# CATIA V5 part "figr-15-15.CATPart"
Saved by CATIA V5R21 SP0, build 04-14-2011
Part number: Part1
Bounding box of the stored display mesh (mm): x -75 to 75, y -66.397 to 33.603, z 0 to 1
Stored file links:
  D:\CATIA V5R21 E-RESOURCES\CATIA-V5R21\catia-v5r21-prt\c15-catia-v5r20-prt\c15-catia-v5r21-figr-15-15.CATPart
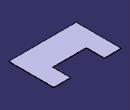
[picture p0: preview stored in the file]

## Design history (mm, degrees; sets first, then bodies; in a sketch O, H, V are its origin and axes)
SheetMetalParameters1: Thickness 1, BendRadius 1, KFactor 0.325257 {= log(min(100,max(20*SheetMetalParameters1.BendRadius,SheetMetalParameters1.Thickness)/SheetMetalParameters1.Thickness))/log(100)/2}, ReliefRadialLength 1, ReliefAxialLength 2, MinimumBendRadius 0
Body1 (main body)
  Sketch1 on xy-plane, origin (0, 0, 0), H (1, 0, 0), V (0, 1, 0)
    line L1 (-37.5, 33.6029) -> (-37.5, -6.3971)
    line L2 (-37.5, -6.3971) -> (37.5, -6.3971)
    line L3 (37.5, -6.3971) -> (37.5, 33.6029)
    line L4 (37.5, 33.6029) -> (75, 33.6029)
    line L5 (75, 33.6029) -> (75, -66.3971)
    line L6 (75, -66.3971) -> (-75, -66.3971)
    line L7 (-75, -66.3971) -> (-75, 33.6029)
    point P8 (-75, 33.6029)
    line L8 (-75, 33.6029) -> (-37.5, 33.6029)
    length L7 = 100
    length L1 = 40
    length L6 = 150
    distance L1 L3 = 75
    vertical: L1 V, L3 V, L5 V, L7 V
    horizontal: L2 H, L4 H, L6 H, L8 H
    coincidence: P8 L4
    symmetry: L7 L5 V, L1 L3 V
  Wall1: Thickness 1, Profile Sketch1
